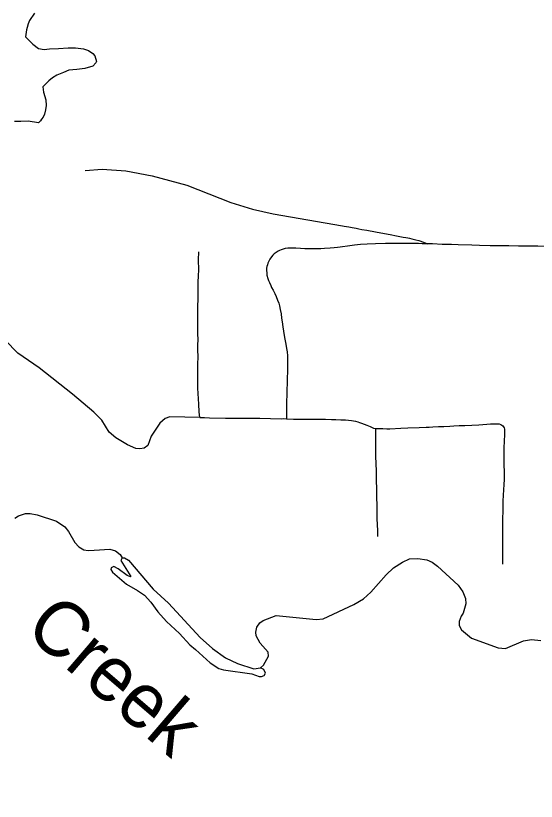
# Model space of a CAD drawing. Extents: x -19 to 366, y -4 to 359.
# Drawn here: x 143.264 to 144.022, y 186.185 to 187.329 of the extents above; entities that cross this region are included whole.
import ezdxf

# ---------------------------------------------------------------- set-up
doc = ezdxf.new("R2010")
doc.units = 0
for name, color, linetype in [('Level 31', 7, 'Continuous'), ('Level 32', 7, 'Continuous'), ('Level 35', 7, 'Continuous'), ('Level 45', 7, 'Continuous'), ('Level 60', 7, 'Continuous')]:
    doc.layers.add(name, color=color, linetype=linetype)

msp = doc.modelspace()

# ---------------------------------------------------------------- linework, layer by layer
at = {"layer": 'Level 31'}
for points in [[(143.8634, 186.9966), (143.861, 186.9966), (143.8579, 186.9967), (143.856, 186.9968), (143.8504, 186.9969), (143.8404, 186.997), (143.8289, 186.997), (143.8148, 186.997), (143.8023, 186.997), (143.7881, 186.9967), (143.7757, 186.9962), (143.7662, 186.9956), (143.7576, 186.9945), (143.7507, 186.9938), (143.7363, 186.9919), (143.7328, 186.9915), (143.7276, 186.9909), (143.7221, 186.9904), (143.7136, 186.9896), (143.7082, 186.9892), (143.6999, 186.9891), (143.6921, 186.9892), (143.6849, 186.9895), (143.679, 186.9899), (143.672, 186.9902), (143.6667, 186.9904), (143.6604, 186.9905), (143.6565, 186.9898), (143.6533, 186.989), (143.6508, 186.9881), (143.648, 186.9869), (143.6463, 186.986), (143.6435, 186.9842), (143.6406, 186.982), (143.6384, 186.9799), (143.6364, 186.9776), (143.634, 186.9741), (143.6325, 186.9715), (143.6312, 186.9684), (143.6305, 186.966), (143.6298, 186.9634), (143.6295, 186.9612), (143.6294, 186.958), (143.6296, 186.9543), (143.63, 186.9512), (143.6312, 186.9461), (143.6323, 186.9432), (143.6335, 186.9405), (143.6357, 186.9357), (143.6368, 186.9332), (143.6389, 186.929), (143.6413, 186.9241), (143.6434, 186.9197), (143.6455, 186.9145), (143.647, 186.9103), (143.6481, 186.9062), (143.6494, 186.9009), (143.6504, 186.8948), (143.6513, 186.8884), (143.652, 186.883), (143.6531, 186.8755), (143.6539, 186.8695), (143.6551, 186.863), (143.6561, 186.8578), (143.6571, 186.8527), (143.658, 186.8474), (143.6586, 186.8441), (143.6592, 186.8394), (143.6599, 186.8335), (143.66, 186.8256), (143.6599, 186.819), (143.6593, 186.7927), (143.6591, 186.7849), (143.6584, 186.7585), (143.6583, 186.753), (143.6585, 186.7418)], [(144.1855, 186.9906), (144.1679, 186.9906), (144.1509, 186.9909), (144.1348, 186.991), (144.1176, 186.9911), (144.1025, 186.9914), (144.0853, 186.9918), (144.0695, 186.9922), (144.0243, 186.9931), (144.0038, 186.9933), (143.9963, 186.9934), (143.9818, 186.9936), (143.9706, 186.9938), (143.9548, 186.9939), (143.9394, 186.9943), (143.928, 186.9947), (143.9082, 186.9952), (143.8986, 186.9954), (143.8849, 186.9958), (143.8708, 186.9964), (143.8634, 186.9966)], [(143.5321, 186.7437), (143.5314, 186.7518), (143.5306, 186.7631), (143.5301, 186.7708), (143.5295, 186.7863), (143.5294, 186.7945), (143.5295, 186.8035), (143.5295, 186.8211), (143.5296, 186.8318), (143.5295, 186.8421), (143.5295, 186.8487), (143.5296, 186.8577), (143.5295, 186.8652), (143.5294, 186.873), (143.5293, 186.8807), (143.5293, 186.8892), (143.5291, 186.8986), (143.5293, 186.9063), (143.5296, 186.9154), (143.5296, 186.9242), (143.5298, 186.9326), (143.5299, 186.9407), (143.5304, 186.9501), (143.5306, 186.9585), (143.5304, 186.9734), (143.5307, 186.9848)], [(143.5321, 186.7437), (143.5389, 186.7436), (143.5461, 186.7434), (143.5698, 186.7428), (143.5762, 186.7428), (143.5825, 186.7428), (143.5915, 186.7427), (143.6046, 186.7426), (143.6122, 186.7426), (143.6198, 186.7425), (143.6505, 186.7419), (143.6545, 186.742), (143.6585, 186.7418)], [(143.6585, 186.7418), (143.6686, 186.7414), (143.675, 186.7414), (143.6827, 186.7412), (143.688, 186.7412), (143.6956, 186.7413), (143.7032, 186.7412), (143.7092, 186.7412), (143.7151, 186.7412), (143.7237, 186.7409), (143.7303, 186.7407), (143.7376, 186.7405), (143.7442, 186.7402), (143.7529, 186.7395), (143.7588, 186.7383), (143.762, 186.7374), (143.7646, 186.7365), (143.7675, 186.7355), (143.7753, 186.7324), (143.7802, 186.7304), (143.7852, 186.7283), (143.7881, 186.7275)], [(143.7881, 186.7275), (143.7887, 186.7274), (143.7907, 186.7274), (143.7943, 186.7275), (143.7985, 186.7274), (143.8044, 186.7273), (143.809, 186.7273), (143.825, 186.7281), (143.8349, 186.7286), (143.8514, 186.7292), (143.8615, 186.7296), (143.8659, 186.7298), (143.8714, 186.73), (143.8794, 186.7304), (143.8872, 186.7307), (143.896, 186.7312), (143.902, 186.7315), (143.9099, 186.7318), (143.9179, 186.732), (143.9283, 186.7324), (143.9384, 186.7329), (143.95, 186.7338), (143.9554, 186.7344), (143.9598, 186.7345), (143.9677, 186.7342), (143.9702, 186.7335), (143.9717, 186.7326), (143.9731, 186.7315), (143.9743, 186.7299), (143.975, 186.7285), (143.9757, 186.7266), (143.9759, 186.7242), (143.9755, 186.7162), (143.9753, 186.7119), (143.9746, 186.6966), (143.9745, 186.6925), (143.9745, 186.6817), (143.9746, 186.6778), (143.9746, 186.677), (143.9748, 186.6733), (143.9751, 186.6658), (143.9753, 186.6535), (143.9749, 186.6461), (143.9739, 186.6304), (143.9734, 186.622), (143.9731, 186.6041), (143.973, 186.5997), (143.9728, 186.585), (143.9729, 186.5773), (143.9729, 186.5629), (143.9729, 186.5552), (143.9729, 186.5459), (143.973, 186.5411), (143.9729, 186.5302)], [(143.7881, 186.7275), (143.788, 186.72), (143.7879, 186.7048), (143.7879, 186.6976), (143.788, 186.6875), (143.7887, 186.6655), (143.7889, 186.6577), (143.7891, 186.6498), (143.7892, 186.6419), (143.7893, 186.6358), (143.7894, 186.6272), (143.7898, 186.6159), (143.7899, 186.609), (143.7901, 186.5951), (143.7903, 186.5889), (143.791, 186.5775), (143.791, 186.5704)]]:
    msp.add_lwpolyline(points, dxfattribs=at)
at = {"layer": 'Level 32'}
msp.add_lwpolyline([(143.3653, 187.1034), (143.39, 187.1052), (143.4247, 187.1028), (143.4627, 187.0958), (143.5132, 187.0822), (143.5772, 187.057), (143.6089, 187.047), (143.6389, 187.0405), (143.74, 187.0227), (143.7425, 187.0223), (143.7492, 187.0212), (143.754, 187.0203), (143.7597, 187.0193), (143.7639, 187.0185), (143.768, 187.0177), (143.7754, 187.0164), (143.788, 187.0141), (143.7958, 187.0127), (143.8094, 187.01), (143.8186, 187.0083), (143.8211, 187.0078), (143.8282, 187.0065), (143.8321, 187.0057), (143.8349, 187.0052), (143.8372, 187.0047), (143.8408, 187.0038), (143.8465, 187.0025), (143.8512, 187.0014), (143.8578, 186.9991), (143.8634, 186.9966)], dxfattribs=at)
at = {"layer": 'Level 35'}
for points in [[(143.2916, 187.3328), (143.2844, 187.3218), (143.2824, 187.3171), (143.2808, 187.3116), (143.2802, 187.3082), (143.2797, 187.305), (143.2786, 187.2981), (143.2893, 187.2875), (143.2975, 187.2809), (143.3058, 187.2796), (143.3136, 187.2806), (143.3267, 187.2813), (143.3404, 187.282), (143.3512, 187.2819), (143.3627, 187.2806), (143.3702, 187.2782), (143.3766, 187.2739), (143.3796, 187.2702), (143.3819, 187.2624), (143.3807, 187.2603), (143.3763, 187.2553), (143.365, 187.2522), (143.3532, 187.2504), (143.3418, 187.2496), (143.334, 187.2462), (143.3243, 187.2424), (143.3177, 187.2383), (143.3123, 187.2341), (143.3065, 187.2281), (143.3035, 187.2255), (143.3048, 187.2173), (143.3082, 187.2064), (143.3084, 187.1979), (143.3078, 187.1918), (143.3061, 187.1856), (143.304, 187.1812), (143.3018, 187.1782), (143.3001, 187.1758), (143.2975, 187.1728), (143.2822, 187.1752), (143.2716, 187.1748), (143.2625, 187.1748)], [(143.2628, 186.5972), (143.2685, 186.6003), (143.2786, 186.6037), (143.2854, 186.6038), (143.2956, 186.6019), (143.3234, 186.5927), (143.3359, 186.5846), (143.3413, 186.5774), (143.3503, 186.5617), (143.356, 186.5553), (143.3636, 186.5509), (143.3695, 186.5498), (143.3784, 186.5506), (143.4013, 186.552), (143.4095, 186.5496), (143.4162, 186.5441), (143.419, 186.5394), (143.4175, 186.5354), (143.4317, 186.5123), (143.4311, 186.5115), (143.4266, 186.5134), (143.4136, 186.5234), (143.407, 186.5266), (143.4034, 186.5247), (143.4028, 186.5221), (143.4051, 186.5183), (143.4253, 186.5007), (143.4414, 186.4918)], [(143.419, 186.5394), (143.4225, 186.5394), (143.4282, 186.536), (143.4644, 186.4935), (143.4865, 186.4734), (143.5326, 186.4233), (143.5509, 186.4074), (143.5694, 186.3937), (143.5869, 186.3854), (143.611, 186.3777), (143.6205, 186.3791)], [(143.4414, 186.4918), (143.4519, 186.4847), (143.4609, 186.4746), (143.4712, 186.4605), (143.4836, 186.4463), (143.5026, 186.4293), (143.5175, 186.4124), (143.5261, 186.4058), (143.5472, 186.3865), (143.5598, 186.3779), (143.5666, 186.376), (143.6078, 186.3701), (143.6188, 186.3662), (143.6222, 186.3662), (143.6258, 186.3677), (143.6277, 186.3715), (143.6254, 186.3766), (143.6205, 186.3791), (143.6248, 186.3827), (143.6322, 186.396), (143.6319, 186.4021), (143.6203, 186.4149), (143.614, 186.4256), (143.6138, 186.4309), (143.6151, 186.4381), (143.6194, 186.4444), (143.6243, 186.4482), (143.6433, 186.4553), (143.7017, 186.4495), (143.7116, 186.4505), (143.7563, 186.4715), (143.7705, 186.4796), (143.7811, 186.4891), (143.8034, 186.5144), (143.8143, 186.5247), (143.8274, 186.533), (143.8374, 186.5376), (143.8494, 186.5382), (143.8628, 186.5365), (143.8704, 186.533), (143.8782, 186.5269), (143.9083, 186.4995), (143.915, 186.4897), (143.9189, 186.4798), (143.9196, 186.4722), (143.9153, 186.4585), (143.9125, 186.4542), (143.9095, 186.4464), (143.9095, 186.4407), (143.9132, 186.4346), (143.9278, 186.4223), (143.9666, 186.4083), (143.9772, 186.4073), (144.0032, 186.4185), (144.0149, 186.4204), (144.0286, 186.4188)]]:
    msp.add_lwpolyline(points, dxfattribs=at)
at = {"layer": 'Level 45'}
msp.add_lwpolyline([(143.5321, 186.7437), (143.4886, 186.7445), (143.4817, 186.7424), (143.4742, 186.7354), (143.4614, 186.7167), (143.4566, 186.7028), (143.4512, 186.6991), (143.4448, 186.698), (143.4389, 186.6986), (143.4272, 186.7039), (143.4101, 186.7141), (143.4005, 186.7221), (143.3898, 186.7397), (143.3781, 186.7515), (143.3471, 186.7776), (143.2985, 186.8161), (143.2675, 186.8375), (143.2489, 186.8562)], dxfattribs=at)
at = {"layer": 'Level 60'}
for points in [[(146.7783, 1.697), (146.5788, 10.3131), (146.3785, 18.9294), (146.1776, 27.5458), (145.9759, 36.1624), (145.7736, 44.7791), (145.5705, 53.396), (145.3668, 62.013), (145.1624, 70.6301), (144.9572, 79.2474), (144.7514, 87.8648), (144.5449, 96.4823), (144.3377, 105.1), (144.1299, 113.7179), (143.9213, 122.3359), (143.712, 130.954), (143.5021, 139.5723), (143.2915, 148.1907), (143.0802, 156.8092), (142.8682, 165.4279), (142.6555, 174.0468), (142.4422, 182.6658), (142.2282, 191.2849), (142.0135, 199.9042), (141.7981, 208.5236), (141.582, 217.1432), (141.3653, 225.7629), (141.1479, 234.3828), (140.9298, 243.0028), (140.711, 251.623), (140.4916, 260.2433), (140.2715, 268.8638), (140.0508, 277.4844), (139.8293, 286.1051), (139.6072, 294.726), (139.3845, 303.3471), (139.161, 311.9683), (138.937, 320.5896), (138.7122, 329.2111), (138.4868, 337.8328), (138.2607, 346.4546)], [(0, 180.8999), (7.1228, 180.9044), (14.2457, 180.9176), (21.3685, 180.9397), (28.4912, 180.9706), (35.614, 181.0103), (42.7366, 181.0589), (49.8592, 181.1163), (56.9818, 181.1825), (64.1042, 181.2575), (71.2266, 181.3414), (78.3488, 181.4341), (85.4709, 181.5357), (92.5929, 181.646), (99.7147, 181.7652), (106.8364, 181.8933), (113.9579, 182.0301), (121.0793, 182.1758), (128.2005, 182.3303), (135.3214, 182.4936), (142.4422, 182.6658), (149.5627, 182.8468), (156.683, 183.0366), (163.8031, 183.2352), (170.9229, 183.4427), (178.0425, 183.659), (185.1617, 183.8841), (192.2807, 184.1181), (199.3994, 184.3608), (206.5178, 184.6124), (213.6359, 184.8728), (220.7537, 185.1421), (227.8711, 185.4201), (234.9881, 185.707), (242.1048, 186.0027), (249.2212, 186.3073), (256.3371, 186.6206), (263.4526, 186.9428), (270.5678, 187.2738), (277.6825, 187.6136), (284.7968, 187.9622), (291.9107, 188.3197), (299.0241, 188.6859), (306.1371, 189.061), (313.2495, 189.4449), (320.3615, 189.8377), (327.4731, 190.2392), (334.5841, 190.6495), (341.6946, 191.0687)]]:
    msp.add_spline(points, degree=3, dxfattribs=at)

# ---------------------------------------------------------------- texts
at = {"layer": 'Level 35'}
msp.add_text('Creek', height=0.08, rotation=319.3735, dxfattribs=at).set_placement((143.2746, 186.4316))

doc.saveas('drawing.dxf')
